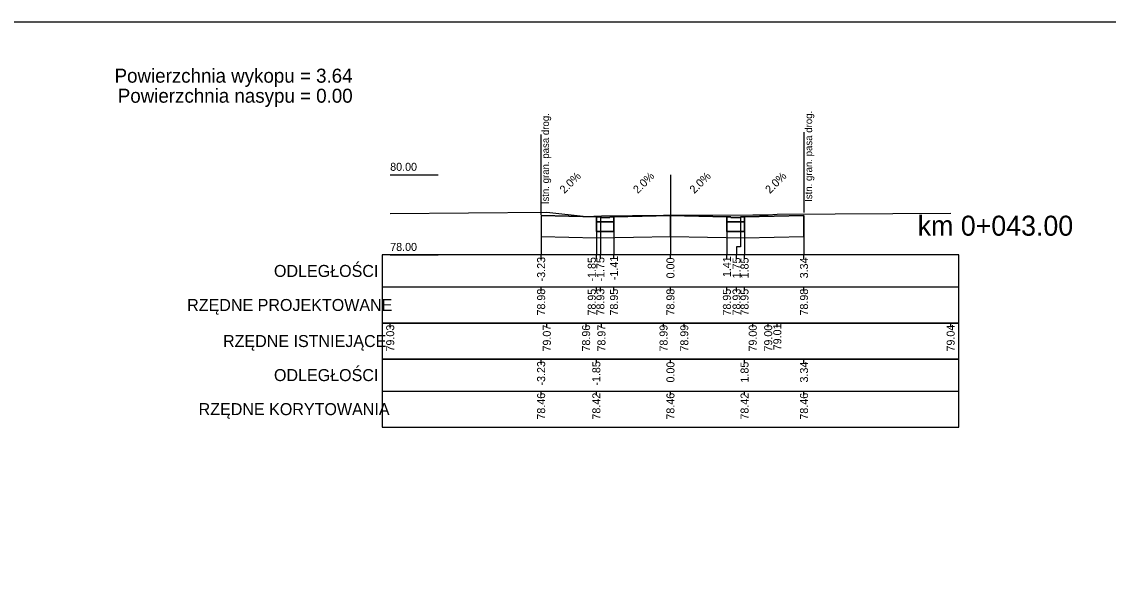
# Model space of a CAD drawing. Extents: x 7492871 to 7493499, y 5802964 to 5802992.
# Drawn here: x 7493132.5 to 7493159.64, y 5802978.41 to 5802992.28 of the extents above; entities that cross this region are included whole.
import ezdxf

# ---------------------------------------------------------------- set-up
doc = ezdxf.new("R2010")
doc.units = 0
for name, color, linetype in [('_wydruk', 7, 'Continuous'), ('d_pop_nasyp_opis', 7, 'Continuous'), ('d_pop_wykop_opis', 7, 'Continuous'), ('opisy_ramki_pop', 7, 'Continuous'), ('pop_comp_kostka', 7, 'Continuous'), ('pop_comp_lawa', 7, 'Continuous'), ('pop_comp_scieralna', 7, 'Continuous'), ('pop_granica_istn', 7, 'Continuous'), ('pop_opis', 7, 'Continuous'), ('pop_os', 7, 'Continuous'), ('pop_pikietaz', 7, 'Continuous'), ('pop_teren', 7, 'Continuous')]:
    doc.layers.add(name, color=color, linetype=linetype)

msp = doc.modelspace()

# ---------------------------------------------------------------- linework, layer by layer
msp.add_lwpolyline([(7493145.476, 5802987.44), (7493146.855, 5802987.413), (7493146.955, 5802987.413), (7493146.956, 5802987.393), (7493147.195, 5802987.393), (7493147.196, 5802987.413), (7493147.296, 5802987.413), (7493148.706, 5802987.441), (7493150.116, 5802987.413), (7493150.216, 5802987.413), (7493150.217, 5802987.393), (7493150.456, 5802987.393), (7493150.457, 5802987.413), (7493150.557, 5802987.413), (7493152.042, 5802987.442)])
at = {"layer": '_wydruk'}
msp.add_lwpolyline([(7492871.369, 5802992.281), (7493499.283, 5802992.281), (7493499.283, 5802963.881), (7492871.369, 5802963.881)], close=True, dxfattribs=at)
at = {"layer": 'opisy_ramki_pop'}
for points in [[(7493145.476, 5802986.92), (7493145.476, 5802986.659), (7493145.476, 5802986.659), (7493145.476, 5802986.459)], [(7493148.706, 5802986.921), (7493148.706, 5802986.659), (7493148.706, 5802986.659), (7493148.706, 5802986.459)], [(7493152.042, 5802986.922), (7493152.042, 5802986.659), (7493152.042, 5802986.659), (7493152.042, 5802986.459)], [(7493146.855, 5802986.884), (7493146.855, 5802986.659), (7493146.855, 5802986.659), (7493146.855, 5802986.459)], [(7493150.557, 5802986.884), (7493150.557, 5802986.659), (7493150.557, 5802986.659), (7493150.557, 5802986.459)]]:
    msp.add_lwpolyline(points, dxfattribs=at)
at = {"layer": 'pop_comp_kostka'}
for p, q in [((7493146.955, 5802987.413), (7493146.855, 5802987.413)), ((7493146.855, 5802987.413), (7493146.855, 5802987.283)), ((7493146.855, 5802987.283), (7493147.296, 5802987.283)), ((7493146.956, 5802987.393), (7493146.955, 5802987.413)), ((7493147.195, 5802987.393), (7493146.956, 5802987.393)), ((7493147.196, 5802987.413), (7493147.195, 5802987.393)), ((7493147.296, 5802987.413), (7493147.196, 5802987.413)), ((7493147.296, 5802987.283), (7493147.296, 5802987.413)), ((7493150.216, 5802987.413), (7493150.116, 5802987.413)), ((7493150.116, 5802987.413), (7493150.116, 5802987.283)), ((7493150.116, 5802987.283), (7493150.557, 5802987.283)), ((7493150.217, 5802987.393), (7493150.216, 5802987.413)), ((7493150.456, 5802987.393), (7493150.217, 5802987.393)), ((7493150.457, 5802987.413), (7493150.456, 5802987.393)), ((7493150.557, 5802987.413), (7493150.457, 5802987.413)), ((7493150.557, 5802987.283), (7493150.557, 5802987.413))]:
    msp.add_line(p, q, dxfattribs=at)
at = {"layer": 'pop_comp_lawa'}
for p, q in [((7493147.296, 5802987.283), (7493146.855, 5802987.283)), ((7493146.855, 5802987.283), (7493146.855, 5802987.043)), ((7493147.296, 5802987.043), (7493147.296, 5802987.283)), ((7493150.557, 5802987.283), (7493150.116, 5802987.283)), ((7493150.116, 5802987.283), (7493150.116, 5802987.043)), ((7493150.557, 5802987.043), (7493150.557, 5802987.283)), ((7493146.855, 5802987.043), (7493147.296, 5802987.043)), ((7493150.116, 5802987.043), (7493150.557, 5802987.043))]:
    msp.add_line(p, q, dxfattribs=at)
at = {"layer": 'pop_comp_scieralna'}
for p, q in [((7493152.042, 5802987.442), (7493150.557, 5802987.413)), ((7493152.042, 5802986.922), (7493152.042, 5802987.442)), ((7493146.855, 5802987.413), (7493145.476, 5802987.44)), ((7493145.476, 5802987.44), (7493145.476, 5802986.92)), ((7493146.855, 5802987.043), (7493146.855, 5802987.413)), ((7493148.706, 5802987.441), (7493147.296, 5802987.413)), ((7493147.296, 5802987.413), (7493147.296, 5802987.043)), ((7493148.706, 5802986.921), (7493148.706, 5802987.441)), ((7493150.116, 5802987.413), (7493148.706, 5802987.441)), ((7493148.706, 5802987.441), (7493148.706, 5802986.921)), ((7493150.116, 5802987.043), (7493150.116, 5802987.413)), ((7493150.557, 5802987.413), (7493150.557, 5802987.043)), ((7493145.476, 5802986.92), (7493146.855, 5802986.884)), ((7493147.296, 5802987.043), (7493146.855, 5802987.043)), ((7493146.855, 5802986.884), (7493148.706, 5802986.921)), ((7493148.706, 5802986.921), (7493150.557, 5802986.884)), ((7493150.557, 5802987.043), (7493150.116, 5802987.043)), ((7493150.557, 5802986.884), (7493152.042, 5802986.922))]:
    msp.add_line(p, q, dxfattribs=at)
at = {"layer": 'pop_granica_istn'}
for p, q in [((7493145.474, 5802987.963), (7493145.474, 5802989.463)), ((7493152.047, 5802988.022), (7493152.047, 5802989.522)), ((7493152.047, 5802987.522), (7493152.047, 5802988.022)), ((7493145.474, 5802987.463), (7493145.474, 5802987.963))]:
    msp.add_line(p, q, dxfattribs=at)
at = {"layer": 'pop_opis'}
for p, q in [((7493141.706, 5802988.459), (7493142.906, 5802988.459)), ((7493141.506, 5802986.459), (7493141.506, 5802984.759)), ((7493141.506, 5802986.459), (7493141.506, 5802984.759)), ((7493141.506, 5802986.459), (7493141.506, 5802984.759)), ((7493141.506, 5802986.459), (7493141.506, 5802984.759)), ((7493141.706, 5802986.459), (7493142.906, 5802986.459)), ((7493145.476, 5802986.359), (7493145.476, 5802986.459)), ((7493146.855, 5802986.359), (7493146.855, 5802986.459)), ((7493146.956, 5802986.359), (7493146.956, 5802986.459)), ((7493147.296, 5802986.359), (7493147.296, 5802986.459)), ((7493148.706, 5802986.359), (7493148.706, 5802986.459)), ((7493150.116, 5802986.359), (7493150.116, 5802986.459)), ((7493150.357, 5802986.359), (7493150.357, 5802986.459)), ((7493150.557, 5802986.359), (7493150.557, 5802986.459)), ((7493152.042, 5802986.359), (7493152.042, 5802986.459)), ((7493141.506, 5802985.659), (7493155.906, 5802985.659)), ((7493141.506, 5802985.659), (7493155.906, 5802985.659)), ((7493141.506, 5802985.659), (7493155.906, 5802985.659)), ((7493141.506, 5802985.659), (7493155.906, 5802985.659)), ((7493145.476, 5802985.559), (7493145.476, 5802985.659)), ((7493146.855, 5802985.559), (7493146.855, 5802985.659)), ((7493146.956, 5802985.559), (7493146.956, 5802985.659)), ((7493147.296, 5802985.559), (7493147.296, 5802985.659)), ((7493148.706, 5802985.559), (7493148.706, 5802985.659)), ((7493150.116, 5802985.559), (7493150.116, 5802985.659)), ((7493150.357, 5802985.559), (7493150.357, 5802985.659)), ((7493150.557, 5802985.559), (7493150.557, 5802985.659)), ((7493152.042, 5802985.559), (7493152.042, 5802985.659)), ((7493141.506, 5802984.759), (7493141.506, 5802983.859)), ((7493141.706, 5802984.659), (7493141.706, 5802984.759)), ((7493145.618, 5802984.659), (7493145.618, 5802984.759)), ((7493146.599, 5802984.659), (7493146.599, 5802984.759)), ((7493146.983, 5802984.659), (7493146.983, 5802984.759)), ((7493148.534, 5802984.659), (7493148.534, 5802984.759)), ((7493149.052, 5802984.659), (7493149.052, 5802984.759)), ((7493150.762, 5802984.659), (7493150.762, 5802984.759)), ((7493151.149, 5802984.659), (7493151.149, 5802984.759)), ((7493151.376, 5802984.659), (7493151.376, 5802984.759)), ((7493155.706, 5802984.659), (7493155.706, 5802984.759)), ((7493141.506, 5802983.859), (7493141.506, 5802982.159)), ((7493145.476, 5802983.759), (7493145.476, 5802983.859)), ((7493146.855, 5802983.759), (7493146.855, 5802983.859)), ((7493148.706, 5802983.759), (7493148.706, 5802983.859)), ((7493150.557, 5802983.759), (7493150.557, 5802983.859)), ((7493152.042, 5802983.759), (7493152.042, 5802983.859)), ((7493141.506, 5802983.059), (7493155.906, 5802983.059)), ((7493145.476, 5802982.959), (7493145.476, 5802983.059)), ((7493146.855, 5802982.959), (7493146.855, 5802983.059)), ((7493148.706, 5802982.959), (7493148.706, 5802983.059)), ((7493150.557, 5802982.959), (7493150.557, 5802983.059)), ((7493152.042, 5802982.959), (7493152.042, 5802983.059))]:
    msp.add_line(p, q, dxfattribs=at)
for points in [[(7493152.042, 5802987.442), (7493152.042, 5802986.659), (7493152.042, 5802986.659), (7493152.042, 5802986.459)], [(7493145.476, 5802987.44), (7493145.476, 5802986.659), (7493145.476, 5802986.659), (7493145.476, 5802986.459)], [(7493146.855, 5802987.413), (7493146.855, 5802986.659), (7493146.855, 5802986.659), (7493146.855, 5802986.459)], [(7493146.956, 5802987.393), (7493146.956, 5802986.659), (7493146.956, 5802986.659), (7493146.956, 5802986.459)], [(7493147.296, 5802987.413), (7493147.296, 5802986.659), (7493147.296, 5802986.659), (7493147.296, 5802986.459)], [(7493148.706, 5802987.441), (7493148.706, 5802986.659), (7493148.706, 5802986.659), (7493148.706, 5802986.459)], [(7493150.116, 5802987.413), (7493150.116, 5802986.659), (7493150.116, 5802986.659), (7493150.116, 5802986.459)], [(7493150.456, 5802987.393), (7493150.456, 5802986.659), (7493150.357, 5802986.659), (7493150.357, 5802986.459)], [(7493150.557, 5802987.413), (7493150.557, 5802986.659), (7493150.557, 5802986.659), (7493150.557, 5802986.459)]]:
    msp.add_lwpolyline(points, dxfattribs=at)
for points in [[(7493141.506, 5802986.459), (7493141.506, 5802984.759), (7493155.906, 5802984.759), (7493155.906, 5802986.459)], [(7493141.506, 5802986.459), (7493141.506, 5802984.759), (7493155.906, 5802984.759), (7493155.906, 5802986.459)], [(7493141.506, 5802986.459), (7493141.506, 5802984.759), (7493155.906, 5802984.759), (7493155.906, 5802986.459)], [(7493141.506, 5802986.459), (7493141.506, 5802984.759), (7493155.906, 5802984.759), (7493155.906, 5802986.459)], [(7493141.506, 5802984.759), (7493141.506, 5802983.859), (7493155.906, 5802983.859), (7493155.906, 5802984.759)], [(7493141.506, 5802983.859), (7493141.506, 5802982.159), (7493155.906, 5802982.159), (7493155.906, 5802983.859)]]:
    msp.add_lwpolyline(points, close=True, dxfattribs=at)
at = {"layer": 'pop_os'}
msp.add_line((7493148.706, 5802988.459), (7493148.706, 5802986.459), dxfattribs=at)
at = {"layer": 'pop_teren'}
msp.add_lwpolyline([(7493141.706, 5802987.491), (7493145.618, 5802987.528), (7493146.599, 5802987.416), (7493146.983, 5802987.431), (7493148.534, 5802987.45), (7493149.052, 5802987.451), (7493150.762, 5802987.461), (7493151.149, 5802987.461), (7493151.376, 5802987.473), (7493155.706, 5802987.498)], dxfattribs=at)

# ---------------------------------------------------------------- texts
at = {"layer": 'd_pop_nasyp_opis'}
msp.add_text('Powierzchnia nasypu = 0.00', height=0.35, dxfattribs=at).set_placement((7493134.901, 5802990.259))
at = {"layer": 'd_pop_wykop_opis'}
msp.add_text('Powierzchnia wykopu = 3.64', height=0.35, dxfattribs=at).set_placement((7493134.82, 5802990.759))
at = {"layer": 'pop_granica_istn'}
for p in [(7493145.673, 5802987.724), (7493152.246, 5802987.783)]:
    msp.add_text('Istn. gran. pasa drog.', height=0.18, rotation=90, dxfattribs=at).set_placement(p)
at = {"layer": 'pop_opis'}
for s, height, p in [('80.00', 0.2, (7493141.706, 5802988.559)), ('78.00', 0.2, (7493141.706, 5802986.559)), ('ODLEGŁOŚCI', 0.3, (7493138.802, 5802985.909)), ('ODLEGŁOŚCI', 0.3, (7493138.802, 5802985.909)), ('ODLEGŁOŚCI', 0.3, (7493138.802, 5802985.909)), ('ODLEGŁOŚCI', 0.3, (7493138.802, 5802985.909)), ('RZĘDNE PROJEKTOWANE', 0.3, (7493136.634, 5802985.059)), ('RZĘDNE PROJEKTOWANE', 0.3, (7493136.634, 5802985.059)), ('RZĘDNE PROJEKTOWANE', 0.3, (7493136.634, 5802985.059)), ('RZĘDNE PROJEKTOWANE', 0.3, (7493136.634, 5802985.059)), ('RZĘDNE ISTNIEJĄCE', 0.3, (7493137.53, 5802984.159)), ('ODLEGŁOŚCI', 0.3, (7493138.802, 5802983.309)), ('RZĘDNE KORYTOWANIA', 0.3, (7493136.92, 5802982.459))]:
    msp.add_text(s, height=height, dxfattribs=at).set_placement(p)
for s, rotation, p in [('2.0%', 45, (7493146.057, 5802987.976)), ('2.0%', 45, (7493147.892, 5802987.977)), ('2.0%', 45, (7493149.302, 5802987.977)), ('2.0%', 45, (7493151.191, 5802987.978)), ('-3.23', 90, (7493145.576, 5802985.798)), ('-1.85', 90, (7493146.841, 5802985.796)), ('-1.75', 90, (7493147.056, 5802985.796)), ('-1.41', 90, (7493147.396, 5802985.829)), ('0.00', 90, (7493148.806, 5802985.874)), ('1.41', 90, (7493150.216, 5802985.905)), ('1.75', 90, (7493150.457, 5802985.873)), ('1.85', 90, (7493150.657, 5802985.873)), ('3.34', 90, (7493152.142, 5802985.874)), ('78.98', 90, (7493145.576, 5802984.946)), ('78.95', 90, (7493146.841, 5802984.945)), ('78.93', 90, (7493147.056, 5802984.947)), ('78.95', 90, (7493147.396, 5802984.945)), ('78.98', 90, (7493148.806, 5802984.946)), ('78.95', 90, (7493150.216, 5802984.945)), ('78.93', 90, (7493150.457, 5802984.947)), ('78.95', 90, (7493150.657, 5802984.945)), ('78.98', 90, (7493152.142, 5802984.946)), ('79.01', 90, (7493151.476, 5802984.078)), ('79.03', 90, (7493141.806, 5802984.047)), ('79.07', 90, (7493145.718, 5802984.047)), ('78.96', 90, (7493146.699, 5802984.047)), ('78.97', 90, (7493147.083, 5802984.047)), ('78.99', 90, (7493148.634, 5802984.046)), ('78.99', 90, (7493149.152, 5802984.046)), ('79.00', 90, (7493150.862, 5802984.047)), ('79.00', 90, (7493151.249, 5802984.047)), ('79.04', 90, (7493155.806, 5802984.047)), ('-3.23', 90, (7493145.576, 5802983.198)), ('-1.85', 90, (7493146.955, 5802983.196)), ('0.00', 90, (7493148.806, 5802983.274)), ('1.85', 90, (7493150.657, 5802983.273)), ('3.34', 90, (7493152.142, 5802983.274)), ('78.46', 90, (7493145.576, 5802982.347)), ('78.42', 90, (7493146.955, 5802982.348)), ('78.46', 90, (7493148.806, 5802982.347)), ('78.42', 90, (7493150.657, 5802982.348)), ('78.46', 90, (7493152.142, 5802982.347))]:
    msp.add_text(s, height=0.2, rotation=rotation, dxfattribs=at).set_placement(p)
at = {"layer": 'pop_pikietaz'}
msp.add_text('km 0+043.00', height=0.5, dxfattribs=at).set_placement((7493154.882, 5802986.939))

doc.saveas('drawing.dxf')
